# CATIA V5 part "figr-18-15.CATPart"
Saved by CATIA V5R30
Part number: Part2
Bounding box of the stored display mesh (mm): x -49.377 to 49.377, y -53.665 to 53.665, z 0 to 34
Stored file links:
  D:\PROJECTS\CATIA V56R 2020\Resources\Parts File\c18_catia_v6_6r2020_prt\figr-18-15.CATPart
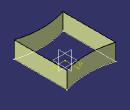
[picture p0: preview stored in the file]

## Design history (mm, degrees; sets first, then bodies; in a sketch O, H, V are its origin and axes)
Body1 (main body)
  Sketch1 on xy-plane, origin (0, 0, 0), H (1, 0, 0), V (0, 1, 0)
    spline S1 through (-49.3771, 53.665) (-5.7754, 46.0634) (49.3771, 53.665)
    line L1 (49.3771, 53.665) -> (49.3771, -53.665)
    point P1 (49.3771, 53.665)
    point P2 (49.3771, -53.665)
    spline S2 through (-49.3771, -53.665) (-5.7754, -46.0634) (49.3771, -53.665)
    point P3 (-49.3771, -53.665)
    point P4 (-49.3771, 53.665)
    line L2 (-49.3771, 53.665) -> (-49.3771, -53.665)
    point P5 (49.3771, 53.665)
    point P6 (49.3771, -53.665)
    point P7 (-49.3771, 53.665)
    point P8 (-49.3771, -53.665)
    point P9 (-5.7754, 46.0634)
    point P10 (-5.7754, -46.0634)
    coincidence: P5 P1, P6 P2, P8 P3
    vertical: L1 V
    symmetry: S1 S2 H, P5 P6 H, P7 P8 H, P9 P10 H, P2 P3 V, P1 P4 V, L1 L2 V
  Extrude1: Element1 Sketch1, Lim1 34, Lim2 0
